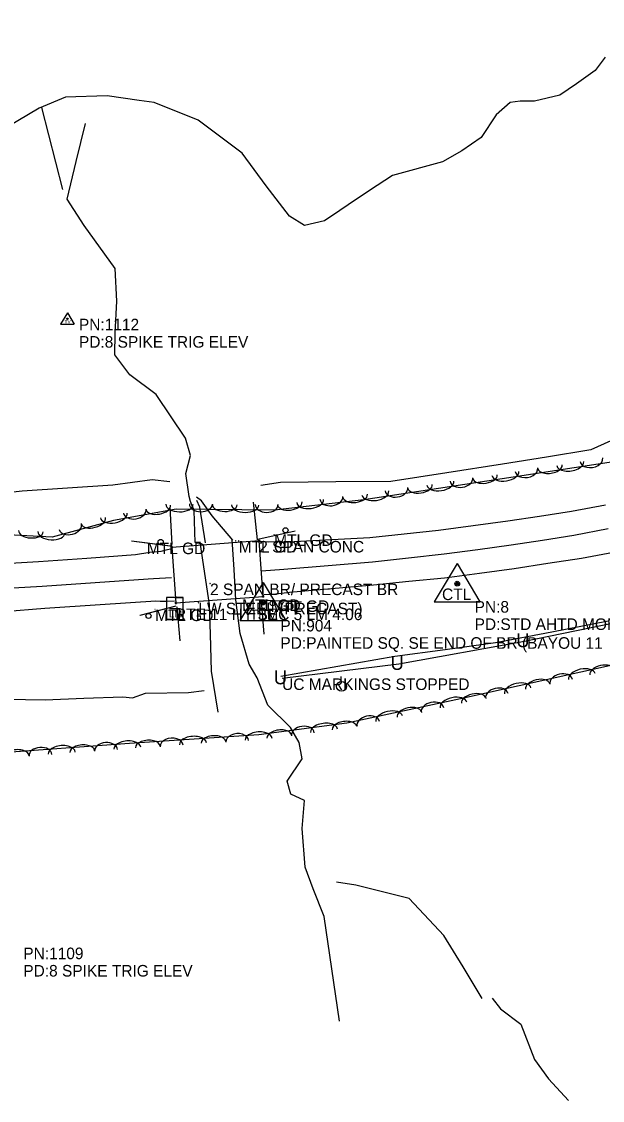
# Model space of a CAD drawing. Extents: x 1451369 to 1458940, y 1868647 to 1875095.
# Drawn here: x 1453451.7 to 1453702.8, y 1870870.8 to 1871337.1 of the extents above; entities that cross this region are included whole.
import ezdxf

# ---------------------------------------------------------------- set-up
doc = ezdxf.new("R2010")
doc.units = 0
for name, color, linetype in [('Default', 7, 'Continuous'), ('E_Const Align', 7, 'Continuous'), ('E_Existing_ROW', 7, 'Continuous'), ('E_Proposed ROW and Easements', 7, 'Continuous'), ('E_Row Point', 7, 'Continuous'), ('E_ROW Point Number', 7, 'Continuous'), ('E_Sheet Border', 7, 'Continuous'), ('E_Station Offset', 7, 'Continuous'), ('E_Survey Point Number', 7, 'Continuous'), ('E_Tract Residual', 7, 'Continuous'), ('R_No Plot', 7, 'Continuous'), ('S_BRIDGE_ANNOT', 7, 'Continuous'), ('S_EDGE_PAVEMENT', 7, 'Continuous'), ('S_EXIST_ROW', 7, 'Continuous'), ('S_GUARDRAIL', 7, 'Continuous'), ('S_LOG_MILE_ANNOT', 7, 'Continuous'), ('S_MISC_STRUCTURES_ANNOT', 7, 'Continuous'), ('S_PAVEMENT_CROWN', 7, 'Continuous'), ('S_PRIMARY_CTL_ANNOT', 7, 'Continuous'), ('S_SECONDARY_CTL_ANNOT', 7, 'Continuous'), ('S_SURVEY_TEXT_ANNOT', 7, 'Continuous'), ('S_UNDERGROUND_CABLE_ANNOT', 7, 'Continuous')]:
    doc.layers.add(name, color=color, linetype=linetype)

msp = doc.modelspace()

# ---------------------------------------------------------------- linework, layer by layer
at = {"layer": 'E_Const Align'}
msp.add_line((1453589.9, 1871051.9), (1453589.9, 1871054.01), dxfattribs=at)
msp.add_circle((1453590.02, 1871049.76), 2.13, dxfattribs=at)
at = {"layer": 'E_Existing_ROW'}
for p, q in [((1453553.65, 1871113.14), (1453552.04, 1871129.34)), ((1453516.78, 1871111.09), (1453515.99, 1871127)), ((1453554.45, 1871112.62), (1453516.66, 1871109.83)), ((1453556.14, 1871088.62), (1453554.45, 1871112.62)), ((1453516.66, 1871109.83), (1453518.47, 1871085.83)), ((1453518.47, 1871085.83), (1453556.14, 1871088.62)), ((1453518.84, 1871084.19), (1453520.15, 1871069.5)), ((1453556.51, 1871072.37), (1453555.4, 1871086.78))]:
    msp.add_line(p, q, dxfattribs=at)
at = {"layer": 'E_Proposed ROW and Easements'}
for points in [[(1453560.91, 1871115.46), (1453560.91, 1871115.51), (1453560.91, 1871115.46), (1453560.86, 1871115.46), (1453560.91, 1871115.46), (1453560.91, 1871115.41), (1453560.91, 1871115.46), (1453560.96, 1871115.46)], [(1453505.87, 1871111.91), (1453505.87, 1871111.96), (1453505.87, 1871111.91), (1453505.82, 1871111.91), (1453505.87, 1871111.91), (1453505.87, 1871111.86), (1453505.87, 1871111.91), (1453505.92, 1871111.91)], [(1453525.33, 1871111.21), (1453525.33, 1871111.26), (1453525.33, 1871111.21), (1453525.28, 1871111.21), (1453525.33, 1871111.21), (1453525.33, 1871111.16), (1453525.33, 1871111.21), (1453525.38, 1871111.21)], [(1453544.3, 1871112.63), (1453544.3, 1871112.68), (1453544.3, 1871112.63), (1453544.25, 1871112.63), (1453544.3, 1871112.63), (1453544.3, 1871112.58), (1453544.3, 1871112.63), (1453544.35, 1871112.63)], [(1453545.59, 1871112.61), (1453545.59, 1871112.66), (1453545.59, 1871112.61), (1453545.54, 1871112.61), (1453545.59, 1871112.61), (1453545.59, 1871112.56), (1453545.59, 1871112.61), (1453545.64, 1871112.61)], [(1453533.18, 1871094.19), (1453533.18, 1871094.24), (1453533.18, 1871094.19), (1453533.13, 1871094.19), (1453533.18, 1871094.19), (1453533.18, 1871094.14), (1453533.18, 1871094.19), (1453533.23, 1871094.19)], [(1453547.07, 1871087.3), (1453547.07, 1871087.35), (1453547.07, 1871087.3), (1453547.02, 1871087.3), (1453547.07, 1871087.3), (1453547.07, 1871087.25), (1453547.07, 1871087.3), (1453547.12, 1871087.3)], [(1453547.09, 1871087.32), (1453547.09, 1871087.37), (1453547.09, 1871087.32), (1453547.04, 1871087.32), (1453547.09, 1871087.32), (1453547.09, 1871087.27), (1453547.09, 1871087.32), (1453547.14, 1871087.32)], [(1453559.46, 1871086.92), (1453559.46, 1871086.97), (1453559.46, 1871086.92), (1453559.41, 1871086.92), (1453559.46, 1871086.92), (1453559.46, 1871086.87), (1453559.46, 1871086.92), (1453559.51, 1871086.92)], [(1453509.42, 1871082.97), (1453509.42, 1871083.02), (1453509.42, 1871082.97), (1453509.37, 1871082.97), (1453509.42, 1871082.97), (1453509.42, 1871082.92), (1453509.42, 1871082.97), (1453509.47, 1871082.97)], [(1453528.14, 1871085.89), (1453528.14, 1871085.94), (1453528.14, 1871085.89), (1453528.09, 1871085.89), (1453528.14, 1871085.89), (1453528.14, 1871085.84), (1453528.14, 1871085.89), (1453528.19, 1871085.89)]]:
    msp.add_lwpolyline(points, dxfattribs=at)
at = {"layer": 'E_Row Point'}
for points in [[(1453516.66, 1871109.83), (1453516.66, 1871110.33), (1453516.66, 1871109.83), (1453516.16, 1871109.83), (1453516.66, 1871109.83), (1453516.66, 1871109.33), (1453516.66, 1871109.83), (1453517.16, 1871109.83)], [(1453554.45, 1871112.62), (1453554.45, 1871113.12), (1453554.45, 1871112.62), (1453553.95, 1871112.62), (1453554.45, 1871112.62), (1453554.45, 1871112.12), (1453554.45, 1871112.62), (1453554.95, 1871112.62)], [(1453556.14, 1871088.62), (1453556.14, 1871089.12), (1453556.14, 1871088.62), (1453555.64, 1871088.62), (1453556.14, 1871088.62), (1453556.14, 1871088.12), (1453556.14, 1871088.62), (1453556.64, 1871088.62)], [(1453518.47, 1871085.83), (1453518.47, 1871086.33), (1453518.47, 1871085.83), (1453517.97, 1871085.83), (1453518.47, 1871085.83), (1453518.47, 1871085.33), (1453518.47, 1871085.83), (1453518.97, 1871085.83)]]:
    msp.add_lwpolyline(points, dxfattribs=at)
at = {"layer": 'E_ROW Point Number'}
for points in [[(1454039.82, 1871337.12), (1453992.45, 1871296.2), (1453976.82, 1871280.78), (1453960.32, 1871268.68), (1453922.85, 1871243.35), (1453886.25, 1871218.61), (1453839.09, 1871189.03), (1453787.52, 1871164.25), (1453741.45, 1871151.98), (1453664.24, 1871140.16), (1453599.61, 1871130.45), (1453561.1, 1871125.93), (1453518.5, 1871126.32), (1453491.52, 1871121.48), (1453464.98, 1871114.18), (1453434.82, 1871115.78), (1453406.63, 1871118.92), (1453377.62, 1871115.67), (1453346.72, 1871118.15), (1453318.09, 1871119.73), (1453254.46, 1871123.88)], [(1453227.7, 1871010.68), (1453313.58, 1871012.86), (1453360.11, 1871017.03), (1453439.31, 1871020.86), (1453498.37, 1871025.17), (1453554.25, 1871028.97), (1453592.3, 1871033.98), (1453641.4, 1871044.5), (1453718.76, 1871061.66), (1453776, 1871072.6), (1453831.69, 1871099.59), (1453853.3, 1871112.04), (1453871.84, 1871109.31), (1453897.32, 1871071.61), (1453935.46, 1870997.61), (1453909.48, 1870975.45), (1453911.54, 1870954.62), (1453910.44, 1870939.28), (1453890.79, 1870936.46), (1453902.73, 1870921.25), (1453921.42, 1870905.04)]]:
    msp.add_lwpolyline(points, dxfattribs=at)
for centre, major_axis, ratio, start_param, end_param in [((1453698, 1871147.74), (4.89, 0.75), 0.685937, 3.141939, 6.283532), ((1453669.93, 1871143.44), (4.89, 0.75), 0.685937, 3.141939, 6.283532), ((1453680.14, 1871144.74), (5.28, 0.81), 0.541194, 3.141797, 6.28339), ((1453688.9, 1871146.08), (5.8, 0.89), 0.550583, 3.141804, 6.283397), ((1453632.72, 1871137.57), (5.8, 0.87), 0.550069, 3.141593, 6.283185), ((1453641.83, 1871139.2), (4.9, 0.74), 0.685297, 3.141593, 6.283185), ((1453652.06, 1871140.47), (5.29, 0.79), 0.540689, 3.141593, 6.283185), ((1453660.83, 1871141.79), (5.8, 0.87), 0.550069, 3.141593, 6.283185), ((1453604.6, 1871133.34), (5.8, 0.87), 0.550069, 3.141593, 6.283185), ((1453613.72, 1871134.98), (4.9, 0.74), 0.685297, 3.141593, 6.283185), ((1453623.95, 1871136.25), (5.29, 0.79), 0.540689, 3.141593, 6.283185), ((1453567.65, 1871128.84), (5.31, 0.62), 0.540688, 3.141593, 6.283185), ((1453576.46, 1871129.87), (5.83, 0.68), 0.550069, 3.141593, 6.283185), ((1453585.62, 1871131.21), (4.92, 0.58), 0.685297, 3.141593, 6.283185), ((1453595.89, 1871132.15), (5.31, 0.62), 0.540688, 3.141593, 6.283185), ((1453491.58, 1871123.65), (5.78, 1.04), 0.550069, 3.141593, 6.283185), ((1453500.65, 1871125.54), (4.88, 0.87), 0.685298, 3.141593, 6.283185), ((1453510.83, 1871127.1), (5.26, 0.94), 0.540689, 3.141593, 6.283185), ((1453519.98, 1871128.43), (5.87, -0.05), 0.550067, 3.141593, 6.283185), ((1453529.24, 1871128.61), (4.96, -0.05), 0.685295, 3.141593, 6.283185), ((1453539.54, 1871128.25), (5.35, -0.05), 0.540687, 3.141593, 6.283185), ((1453548.4, 1871128.17), (5.87, -0.05), 0.550067, 3.141593, 6.283185), ((1453557.66, 1871128.35), (4.96, -0.05), 0.685295, 3.141593, 6.283185), ((1453472.83, 1871118.81), (4.78, 1.32), 0.685299, 3.141593, 6.283185), ((1453482.83, 1871121.29), (5.15, 1.42), 0.54069, 3.141593, 6.283185), ((1453455.78, 1871116.79), (5.34, -0.28), 0.540687, 3.141593, 6.283185), ((1453464.63, 1871116.32), (5.86, -0.31), 0.550067, 3.141593, 6.283185), ((1453702.57, 1871055.9), (-5.22, -1.16), 0.540698, 3.141593, 6.283185), ((1453684.93, 1871051.72), (-4.84, -1.07), 0.685309, 3.141593, 6.283185), ((1453693.91, 1871053.98), (-5.73, -1.27), 0.550078, 3.141593, 6.283185), ((1453666.16, 1871047.82), (-5.73, -1.27), 0.550078, 3.141593, 6.283185), ((1453674.81, 1871049.74), (-5.22, -1.16), 0.540698, 3.141593, 6.283185), ((1453638.38, 1871041.68), (-5.74, -1.23), 0.550078, 3.141593, 6.283185), ((1453647.06, 1871043.58), (-5.22, -1.16), 0.540698, 3.141593, 6.283185), ((1453657.18, 1871045.56), (-4.84, -1.07), 0.685309, 3.141593, 6.283185), ((1453619.26, 1871037.58), (-5.23, -1.12), 0.540698, 3.141593, 6.283185), ((1453629.38, 1871039.49), (-4.85, -1.04), 0.685309, 3.141593, 6.283185), ((1453601.59, 1871033.53), (-4.85, -1.04), 0.685309, 3.141593, 6.283185), ((1453610.59, 1871035.73), (-5.74, -1.23), 0.550078, 3.141593, 6.283185), ((1453563.09, 1871028), (-5.3, -0.7), 0.5407, 3.141599, 6.283192), ((1453573.34, 1871029.08), (-4.91, -0.65), 0.685312, 3.141604, 6.283196), ((1453582.48, 1871030.55), (-5.82, -0.77), 0.550081, 3.141599, 6.283192), ((1453591.27, 1871031.7), (-5.3, -0.7), 0.5407, 3.141599, 6.283192), ((1453497.45, 1871022.97), (-5.85, -0.43), 0.550162, 3.141632, 6.283225), ((1453506.29, 1871023.58), (-5.33, -0.36), 0.540761, 3.141627, 6.28322), ((1453516.58, 1871024.02), (-4.94, -0.34), 0.685389, 3.14165, 6.283243), ((1453525.8, 1871024.91), (-5.85, -0.4), 0.550143, 3.141628, 6.283221), ((1453534.65, 1871025.51), (-5.33, -0.36), 0.540761, 3.141627, 6.28322), ((1453544.94, 1871025.95), (-4.94, -0.34), 0.685389, 3.14165, 6.283243), ((1453554.16, 1871026.84), (-5.85, -0.4), 0.550143, 3.141628, 6.283221), ((1453449.6, 1871019.49), (-5.33, -0.39), 0.54078, 3.141631, 6.283224), ((1453459.89, 1871019.97), (-4.94, -0.36), 0.685413, 3.141658, 6.28325), ((1453469.11, 1871020.91), (-5.85, -0.43), 0.550162, 3.141632, 6.283225), ((1453477.95, 1871021.55), (-5.33, -0.39), 0.54078, 3.141631, 6.283224), ((1453488.24, 1871022.04), (-4.94, -0.36), 0.685413, 3.141658, 6.28325)]:
    msp.add_ellipse(centre, major_axis=major_axis, ratio=ratio, start_param=start_param, end_param=end_param, dxfattribs=at)
at = {"layer": 'E_Sheet Border'}
for p, q in [((1453518.02, 1871088.19), (1453521.62, 1871088.19)), ((1453515.62, 1871083.39), (1453520.42, 1871083.39)), ((1453518.02, 1871078.59), (1453514.42, 1871078.59))]:
    msp.add_line(p, q, dxfattribs=at)
msp.add_lwpolyline([(1453521.62, 1871088.19), (1453514.42, 1871088.19), (1453514.42, 1871078.59), (1453521.62, 1871078.59)], close=True, dxfattribs=at)
at = {"layer": 'E_Station Offset'}
for p, q in [((1453471.52, 1871211.27), (1453468.51, 1871206.31)), ((1453471.52, 1871211.27), (1453474.47, 1871206.31)), ((1453468.51, 1871206.31), (1453474.47, 1871206.31))]:
    msp.add_line(p, q, dxfattribs=at)
for radius in [0.311, 0.183, 0.103]:
    msp.add_circle((1453471.52, 1871208.66), radius, dxfattribs=at)
at = {"layer": 'E_Survey Point Number'}
for p, q in [((1453732.49, 1871082.08), (1453669.13, 1871069.18)), ((1453669.13, 1871069.18), (1453614.82, 1871059.4)), ((1453614.82, 1871059.4), (1453564.34, 1871053.18))]:
    msp.add_line(p, q, dxfattribs=at)
at = {"layer": 'E_Tract Residual'}
for points in [[(1453703.9, 1871321.79), (1453699.57, 1871315.92), (1453691.57, 1871310.2), (1453684.3, 1871305.3), (1453673.48, 1871302.77), (1453667.17, 1871302.7), (1453662.88, 1871302.12), (1453656.91, 1871296.83), (1453650.4, 1871286.96), (1453641.98, 1871281.23), (1453633.61, 1871276.43), (1453611.98, 1871270.63), (1453605.35, 1871266.29), (1453596.54, 1871260.33), (1453589.3, 1871255.44), (1453582.72, 1871251.03), (1453574.04, 1871248.94), (1453567.51, 1871252.97), (1453557.43, 1871266.1), (1453547.09, 1871280.27), (1453528.1, 1871294.5), (1453509.11, 1871302.21), (1453502.57, 1871302.97), (1453488.69, 1871304.97), (1453470.77, 1871304.42), (1453459.28, 1871299.74), (1453445.55, 1871291.53)], [(1453460.39, 1871299.91), (1453469.36, 1871264.53)], [(1453655.09, 1870915.01), (1453658.67, 1870910.4), (1453667.52, 1870903.72), (1453673.37, 1870888.52), (1453679.49, 1870880.17), (1453688.11, 1870870.77)]]:
    msp.add_lwpolyline(points, dxfattribs=at)
at = {"layer": 'R_No Plot'}
for p, q in [((1453640.03, 1871102.83), (1453630, 1871086.32)), ((1453640.03, 1871102.83), (1453649.86, 1871086.32)), ((1453556.1, 1871094.7), (1453546.07, 1871078.19)), ((1453556.1, 1871094.7), (1453565.93, 1871078.19)), ((1453630, 1871086.32), (1453649.86, 1871086.32)), ((1453546.07, 1871078.19), (1453565.93, 1871078.19))]:
    msp.add_line(p, q, dxfattribs=at)
for centre, radius in [((1453640.03, 1871094.13), 1.04), ((1453640.03, 1871094.13), 0.609), ((1453640.03, 1871094.13), 0.344), ((1453556.1, 1871086), 1.04), ((1453556.1, 1871086), 0.609), ((1453556.1, 1871086), 0.344)]:
    msp.add_circle(centre, radius, dxfattribs=at)
at = {"layer": 'S_EDGE_PAVEMENT'}
for points in [[(1453704.08, 1871128.1), (1453689.39, 1871125.27), (1453675.61, 1871123.23), (1453661.83, 1871121.2), (1453646.86, 1871119.17), (1453631.9, 1871117.14), (1453617.08, 1871115.54), (1453602.26, 1871113.94), (1453583.14, 1871112.92), (1453564.02, 1871111.9), (1453562.2, 1871112.18), (1453558.5, 1871112.11), (1453554.74, 1871112.36)], [(1453516.76, 1871109.25), (1453514.06, 1871108.59), (1453511.89, 1871108.05), (1453507.1, 1871107.59), (1453500.92, 1871106.65), (1453479.96, 1871105.09), (1453458.99, 1871103.52), (1453441.73, 1871102.54), (1453424.48, 1871101.57), (1453424.17, 1871101.65), (1453401.1, 1871099.91), (1453378.02, 1871098.17), (1453365.52, 1871097.26), (1453353.01, 1871096.35), (1453340.51, 1871095.43), (1453328, 1871094.52), (1453315.15, 1871093.52), (1453302.3, 1871092.52), (1453289.45, 1871091.52), (1453276.6, 1871090.52)], [(1453707.59, 1871107.68), (1453693.75, 1871105.05), (1453679.18, 1871102.8), (1453664.62, 1871100.54), (1453649.58, 1871098.53), (1453634.54, 1871096.51), (1453619.16, 1871095.04), (1453603.78, 1871093.56), (1453585.64, 1871091.92), (1453567.49, 1871090.28), (1453561.59, 1871089.6), (1453556.6, 1871089.33)], [(1453517.83, 1871086.64), (1453514.52, 1871086.48), (1453511.59, 1871086.48), (1453509.8, 1871086.63), (1453485.77, 1871085.05), (1453461.74, 1871083.48), (1453444.02, 1871081.98), (1453426.3, 1871080.48), (1453426.25, 1871081.01), (1453402.95, 1871079.42), (1453379.65, 1871077.82), (1453366.86, 1871076.91), (1453354.06, 1871075.99), (1453341.27, 1871075.08), (1453328.48, 1871074.16), (1453315.89, 1871073.15), (1453303.31, 1871072.14), (1453290.72, 1871071.13), (1453278.14, 1871070.11)]]:
    msp.add_lwpolyline(points, dxfattribs=at)
at = {"layer": 'S_EXIST_ROW'}
for points in [[(1453536.72, 1871038.63), (1453533.79, 1871056.28), (1453533.42, 1871072.29), (1453532.98, 1871085.09), (1453530.97, 1871098.61), (1453528.96, 1871112.12), (1453526.72, 1871111.93), (1453526.26, 1871125.72), (1453524.74, 1871129.64), (1453524.2, 1871131.78), (1453522.72, 1871141.82), (1453524.8, 1871149.52), (1453522.57, 1871157.05), (1453509.84, 1871175.94), (1453498.55, 1871184.42), (1453491.98, 1871193.1), (1453492.23, 1871202.5), (1453492.89, 1871216.3), (1453492.25, 1871230.34), (1453478.76, 1871248.91), (1453471.38, 1871260.36), (1453475.38, 1871276.67), (1453479.39, 1871292.99)], [(1453719.25, 1871161.58), (1453697.72, 1871151.97), (1453678.67, 1871148.89), (1453659.62, 1871145.8), (1453635.5, 1871142.07), (1453611.39, 1871138.34), (1453587.52, 1871138.13), (1453563.65, 1871137.92), (1453555.08, 1871136.59)], [(1453234.64, 1871117.61), (1453255.43, 1871118.69), (1453276.22, 1871119.77), (1453297.02, 1871120.84), (1453317.81, 1871121.92), (1453333.04, 1871123), (1453348.27, 1871124.09), (1453363.5, 1871125.17), (1453378.73, 1871126.25), (1453397.03, 1871128.25), (1453415.33, 1871130.24), (1453433.63, 1871132.24), (1453451.93, 1871134.23), (1453471.53, 1871135.57), (1453491.13, 1871136.9), (1453508.21, 1871139.22), (1453515.88, 1871138.37)], [(1453558.23, 1871041.56), (1453553.54, 1871053.42), (1453550.15, 1871059.34), (1453546.19, 1871072.67), (1453544.35, 1871087.12), (1453543.57, 1871100.21), (1453542.8, 1871113.3), (1453543.06, 1871112.98), (1453534.12, 1871123.41), (1453529.56, 1871129.98), (1453527.38, 1871131.59)], [(1453531.29, 1871111.83), (1453528.82, 1871127.2), (1453527.54, 1871130.09)], [(1453705.28, 1871077.87), (1453680.9, 1871073.2), (1453656.51, 1871068.54), (1453634.77, 1871065.58), (1453613.02, 1871062.62), (1453588.4, 1871058.31), (1453563.79, 1871054)], [(1453353.34, 1871042.99), (1453376.48, 1871045.45), (1453389.36, 1871045.2), (1453402.24, 1871044.95), (1453415.11, 1871044.69), (1453427.99, 1871044.44), (1453444.99, 1871044.21), (1453461.99, 1871043.99), (1453478.71, 1871044.62), (1453495.43, 1871045.25), (1453499.7, 1871044.86), (1453505.3, 1871046.74), (1453523.93, 1871047.07), (1453530.6, 1871047.92)], [(1453558.23, 1871041.56), (1453567.92, 1871031.92)], [(1453589.2, 1870905.06), (1453585.83, 1870927.66), (1453582.47, 1870950.26), (1453577.7, 1870962.16), (1453574.24, 1870971.66), (1453572.99, 1870988.38), (1453574.01, 1871000.48), (1453568.06, 1871003.16), (1453566.51, 1871008.8), (1453573.02, 1871018.38), (1453571.71, 1871025.51), (1453567.92, 1871031.92)], [(1453650.87, 1870914.89), (1453642.55, 1870928.49), (1453634.23, 1870942.09), (1453619.28, 1870958.01), (1453596.22, 1870963.75), (1453587.89, 1870965.13)]]:
    msp.add_lwpolyline(points, dxfattribs=at)
at = {"layer": 'S_GUARDRAIL'}
for points in [[(1453553.85, 1871113.42), (1453569.98, 1871117.02)], [(1453553.85, 1871113.42), (1453566.05, 1871116.15)], [(1453566.05, 1871116.15), (1453569.98, 1871117.02)], [(1453499.31, 1871112.65), (1453511.71, 1871111.08)], [(1453499.31, 1871112.65), (1453517.02, 1871110.4)], [(1453511.71, 1871111.08), (1453517.02, 1871110.4)], [(1453560.28, 1871086.78), (1453555.36, 1871087.03)], [(1453572.76, 1871086.15), (1453555.36, 1871087.03)], [(1453518.38, 1871084.49), (1453502.8, 1871080.36)], [(1453518.38, 1871084.49), (1453506.3, 1871081.29)], [(1453572.76, 1871086.15), (1453560.28, 1871086.78)], [(1453506.3, 1871081.29), (1453502.8, 1871080.36)]]:
    msp.add_lwpolyline(points, dxfattribs=at)
for centre in [(1453565.81, 1871117.22), (1453511.85, 1871112.17), (1453506.58, 1871080.22)]:
    msp.add_circle(centre, 1.1, dxfattribs=at)
msp.add_ellipse((1453560.23, 1871085.68), major_axis=(-0.06, -1.1), ratio=0.999642, dxfattribs=at)
at = {"layer": 'S_PAVEMENT_CROWN'}
for points in [[(1453705.26, 1871117.89), (1453690.39, 1871114.91), (1453676.86, 1871112.85), (1453663.33, 1871110.8), (1453648.86, 1871108.81), (1453634.38, 1871106.83), (1453618.92, 1871105.17), (1453603.46, 1871103.51), (1453584.29, 1871101.87), (1453565.12, 1871100.24), (1453555.47, 1871099.53)], [(1453516.6, 1871096.69), (1453508.81, 1871096.3), (1453506.4, 1871096.05), (1453483.5, 1871094.52), (1453460.6, 1871092.98), (1453443.09, 1871091.87), (1453425.57, 1871090.77), (1453402.13, 1871089.07), (1453378.68, 1871087.38), (1453366.08, 1871086.5), (1453353.48, 1871085.63), (1453340.88, 1871084.75), (1453328.29, 1871083.88), (1453315.66, 1871082.83), (1453303.04, 1871081.78), (1453290.41, 1871080.74), (1453277.79, 1871079.69)]]:
    msp.add_lwpolyline(points, dxfattribs=at)

# ---------------------------------------------------------------- texts
at = {"layer": 'Default'}
for p in [(1453665.5, 1871066.64), (1453611.19, 1871056.85), (1453560.72, 1871050.63)]:
    msp.add_text('U', height=6, rotation=360, dxfattribs=at).set_placement(p)
at = {"layer": 'E_Sheet Border'}
msp.add_text('LM', height=3, rotation=360, dxfattribs=at).set_placement((1453515.48, 1871079.55))
at = {"layer": 'E_Station Offset'}
msp.add_text('TV', height=1.5, rotation=360, dxfattribs=at).set_placement((1453470.32, 1871206.64))
at = {"layer": 'R_No Plot'}
for s, height, p in [('CTL', 5, (1453633.45, 1871087.05)), ('TBM', 4.287, (1453550.45, 1871078.61))]:
    msp.add_text(s, height=height, rotation=360, dxfattribs=at).set_placement(p)
at = {"layer": 'S_BRIDGE_ANNOT'}
msp.add_text('2 SPAN CONC', height=5, dxfattribs=at).set_placement((1453554.45, 1871107.62))
at = {"layer": 'S_LOG_MILE_ANNOT'}
msp.add_text('RTE 11 HY SEC 5 LM 4.06', height=5, dxfattribs=at).set_placement((1453518.02, 1871078.39))
at = {"layer": 'S_MISC_STRUCTURES_ANNOT'}
msp.add_text('LW STEEL (PRECAST)', height=5, dxfattribs=at).set_placement((1453528.14, 1871080.89))
at = {"layer": 'S_PRIMARY_CTL_ANNOT'}
for s, p in [('PN:8', (1453647.53, 1871081.63)), ('PN:904', (1453563.6, 1871073.5)), ('PD:STD AHTD MON STAMPED PN:8 11', (1453647.53, 1871074.13)), ('PD:PAINTED SQ. SE END OF BR (BAYOU 11', (1453563.6, 1871066))]:
    msp.add_text(s, height=5, dxfattribs=at).set_placement(p)
at = {"layer": 'S_SECONDARY_CTL_ANNOT'}
for s, p in [('PN:1112', (1453476.52, 1871203.66)), ('PD:8 SPIKE TRIG ELEV', (1453476.52, 1871196.16)), ('PN:1109', (1453452.47, 1870931.82)), ('PD:8 SPIKE TRIG ELEV', (1453452.47, 1870924.32))]:
    msp.add_text(s, height=5, dxfattribs=at).set_placement(p)
at = {"layer": 'S_SURVEY_TEXT_ANNOT'}
for s, p in [('MTL GD', (1453560.91, 1871110.46)), ('MTL GD', (1453505.87, 1871106.91)), ('MTL GD', (1453545.59, 1871107.61)), ('2 SPAN BR/ PRECAST BR', (1453533.18, 1871089.19)), ('MTL GD', (1453547.09, 1871082.32)), ('MTL GD', (1453559.46, 1871081.92)), ('MTL GD', (1453509.42, 1871077.97))]:
    msp.add_text(s, height=5, dxfattribs=at).set_placement(p)
at = {"layer": 'S_UNDERGROUND_CABLE_ANNOT'}
msp.add_text('UC MARKINGS STOPPED', height=5, dxfattribs=at).set_placement((1453564.34, 1871048.18))

doc.saveas('drawing.dxf')
